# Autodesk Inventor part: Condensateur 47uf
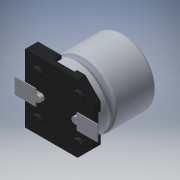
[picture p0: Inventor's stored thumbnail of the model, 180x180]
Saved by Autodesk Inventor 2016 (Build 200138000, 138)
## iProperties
Created: 2018-03
Part Number: Condensateur 47uf
Material: Générique
Document SubType Name: Modeling
Designer: Bruno
Density: 1 g/cm^3
Appearance: Par défaut
Author: Bruno
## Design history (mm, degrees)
feature "Composite1"
body "Srf1"
